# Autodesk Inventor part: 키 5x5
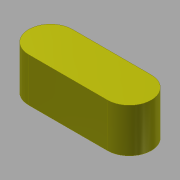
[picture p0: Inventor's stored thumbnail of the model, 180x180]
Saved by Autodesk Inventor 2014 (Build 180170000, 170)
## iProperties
Created: 2014-10
Part Number: 키 5x5
Document SubType Name: Modeling
Designer: KYOUNG IL JANG
Density: 7.86 g/cm^3
Mass: 2.54015 g
Surface Area: 2.9781 cm^2
Volume: 0.323175 cm^3
Material: 강철, 연강
Appearance: 노란색
Author: SeoGD™ [www.esajin.kr]
Revision Number: 1
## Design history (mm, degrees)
sketch "스케치1"
  geometry: L1 (-4.5, -2.5)-(4.5, -2.5); L2 (4.5, 2.5)-(-4.5, 2.5); A1 r 2.5 centre (4.5, 0) between (4.5, -2.5) and (4.5, 2.5); A2 r 2.5 centre (-4.5, 0) between (-4.5, 2.5) and (-4.5, -2.5); 2 further points
  constraints: 4 end point, 4 point on circle, 4 tangent, 2 centre point, 1 horizontal, 1 horizontal alignment, 1 midpoint, 1 parallel, 1 vertical alignment
  dimensions: "d0" = 5 distance between parallel lines of L1 L2; "d1" = 14 dimension on A1 A2
extrude "돌출1" new body sketch "스케치1" stored distance "d2" = 5; taper "d3" = 0 deg
node "솔리드1"
